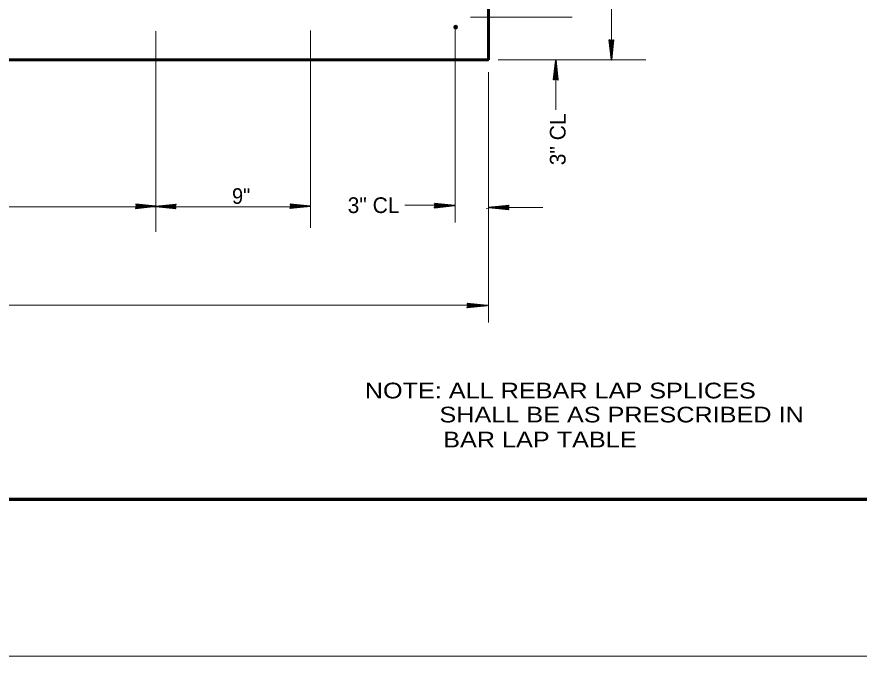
# Model space of a CAD drawing. Extents: x 4.49 to 7.69, y 0.28 to 2.27.
# Drawn here: x 5.2955 to 5.7423, y 0.2828 to 0.6219 of the extents above; entities that cross this region are included whole.
import ezdxf

# ---------------------------------------------------------------- set-up
doc = ezdxf.new("R2010")
doc.units = 0
doc.header["$LTSCALE"] = 0.0033
doc.header["$PDMODE"] = 32
doc.header["$PDSIZE"] = 0.00165
doc.layers.add('1', color=7, linetype='Continuous', lineweight=35)

msp = doc.modelspace()

# ---------------------------------------------------------------- linework, layer by layer
at = {"layer": '1', "lineweight": 13}
for p, q in [((5.610917, 1.013917), (5.610917, 0.599083)), ((5.536083, 0.62175), (5.590083, 0.62175)), ((5.528083, 0.617583), (5.528083, 0.51275)), ((5.369333, 0.61425), (5.369333, 0.512083)), ((5.45125, 0.614583), (5.45125, 0.513417)), ((5.528083, 0.609417), (5.528083, 0.607833)), ((5.54575, 0.599083), (5.54575, 0.59875)), ((5.55075, 0.599083), (5.629083, 0.599083)), ((5.54575, 0.592583), (5.54575, 0.510833)), ((5.581333, 0.572583), (5.581333, 0.589083)), ((5.448417, 0.521167), (4.897333, 0.521167)), ((5.50125, 0.522), (5.522083, 0.522)), ((5.544583, 0.52025), (5.545167, 0.52025)), ((5.55375, 0.52075), (5.574583, 0.52075)), ((5.45125, 0.51575), (5.45125, 0.51)), ((5.369333, 0.513083), (5.369333, 0.507833)), ((5.54575, 0.512417), (5.54575, 0.45975)), ((5.179917, 0.469), (5.545333, 0.469)), ((7.689167, 0.28275), (4.492417, 0.28275))]:
    msp.add_line(p, q, dxfattribs=at)
at = {"layer": '1'}
for p, q in [((5.609833, 0.609417), (5.610667, 0.602083)), ((5.61, 0.609417), (5.61075, 0.602083)), ((5.610083, 0.609417), (5.610917, 0.602083)), ((5.61025, 0.6095), (5.611, 0.602167)), ((5.61175, 0.609417), (5.61075, 0.601583)), ((5.610917, 0.609667), (5.610917, 0.599083)), ((5.61175, 0.609417), (5.610917, 0.601583)), ((5.611917, 0.609417), (5.611, 0.601583)), ((5.611917, 0.609417), (5.611, 0.601583)), ((5.611833, 0.609417), (5.611, 0.601583)), ((5.581333, 0.588417), (5.581333, 0.599)), ((5.580333, 0.588667), (5.58125, 0.5965)), ((5.580333, 0.588667), (5.58125, 0.5965)), ((5.580417, 0.588667), (5.58125, 0.5965)), ((5.5805, 0.588667), (5.581333, 0.5965)), ((5.5805, 0.588667), (5.5815, 0.5965)), ((5.582, 0.588583), (5.58125, 0.595917)), ((5.582167, 0.588667), (5.581333, 0.596)), ((5.58225, 0.588667), (5.5815, 0.596)), ((5.582417, 0.588667), (5.581583, 0.596)), ((5.51725, 0.522833), (5.525083, 0.521917)), ((5.51725, 0.522833), (5.525083, 0.521917)), ((5.51725, 0.52275), (5.525083, 0.521917)), ((5.358583, 0.521417), (5.369167, 0.521417)), ((5.35875, 0.52075), (5.366083, 0.5215)), ((5.358833, 0.522417), (5.366667, 0.5215)), ((5.358833, 0.522417), (5.366667, 0.5215)), ((5.358833, 0.522333), (5.366667, 0.5215)), ((5.358833, 0.52225), (5.366667, 0.521417)), ((5.358833, 0.52225), (5.366667, 0.52125)), ((5.358833, 0.520583), (5.366167, 0.521417)), ((5.358833, 0.5205), (5.366167, 0.52125)), ((5.358833, 0.520333), (5.366167, 0.521167)), ((5.379917, 0.52125), (5.369333, 0.52125)), ((5.379667, 0.520417), (5.371833, 0.521417)), ((5.379667, 0.520417), (5.371833, 0.52125)), ((5.379667, 0.52025), (5.371833, 0.521167)), ((5.379667, 0.52025), (5.371833, 0.521167)), ((5.379667, 0.520333), (5.371833, 0.521167)), ((5.379667, 0.522333), (5.372333, 0.5215)), ((5.379667, 0.522167), (5.372333, 0.521417)), ((5.379667, 0.522083), (5.372333, 0.52125)), ((5.37975, 0.521917), (5.372417, 0.521167)), ((5.4405, 0.5215), (5.451083, 0.5215)), ((5.440667, 0.520833), (5.448, 0.521583)), ((5.44075, 0.5225), (5.448583, 0.521583)), ((5.44075, 0.5225), (5.448583, 0.521583)), ((5.44075, 0.522417), (5.448583, 0.521583)), ((5.44075, 0.522333), (5.448583, 0.5215)), ((5.44075, 0.522333), (5.448583, 0.521333)), ((5.44075, 0.520667), (5.448083, 0.5215)), ((5.44075, 0.520583), (5.448083, 0.521333)), ((5.44075, 0.520417), (5.448083, 0.52125)), ((5.517, 0.521833), (5.527583, 0.521833)), ((5.517167, 0.521167), (5.5245, 0.521917)), ((5.51725, 0.522667), (5.525083, 0.521833)), ((5.51725, 0.522667), (5.525083, 0.521667)), ((5.51725, 0.521), (5.524583, 0.521833)), ((5.51725, 0.520917), (5.524583, 0.521667)), ((5.51725, 0.52075), (5.524583, 0.521583)), ((5.556417, 0.52075), (5.545833, 0.52075)), ((5.556167, 0.519917), (5.548333, 0.520917)), ((5.556167, 0.519917), (5.548333, 0.52075)), ((5.556167, 0.51975), (5.548333, 0.520667)), ((5.556167, 0.51975), (5.548333, 0.520667)), ((5.556167, 0.519833), (5.548333, 0.520667)), ((5.556167, 0.521833), (5.548833, 0.521)), ((5.556167, 0.521667), (5.548833, 0.520917)), ((5.556167, 0.521583), (5.548833, 0.52075)), ((5.55625, 0.521417), (5.548917, 0.520667)), ((5.534583, 0.469833), (5.542417, 0.468917)), ((5.534583, 0.469833), (5.542417, 0.468917)), ((5.534583, 0.46975), (5.542417, 0.468917)), ((5.534583, 0.469667), (5.542417, 0.468833)), ((5.534583, 0.469667), (5.542417, 0.468667)), ((5.534333, 0.468833), (5.544917, 0.468833)), ((5.5345, 0.468167), (5.541833, 0.468917)), ((5.534583, 0.468), (5.541917, 0.468833)), ((5.534583, 0.467917), (5.541917, 0.468667)), ((5.534583, 0.46775), (5.541917, 0.468583))]:
    msp.add_line(p, q, dxfattribs=at)
at = {"layer": '1', "lineweight": 60}
msp.add_line((5.54575, 0.599083), (5.122333, 0.599083), dxfattribs=at)
at = {"layer": '1', "lineweight": 70}
msp.add_line((4.659167, 0.366083), (7.605833, 0.366083), dxfattribs=at)
at = {"layer": '1', "lineweight": 60}
msp.add_lwpolyline([(5.462417, 1.01575), (5.462417, 0.682417), (5.54575, 0.682417), (5.54575, 0.599083)], dxfattribs=at)
at = {"layer": '1', "lineweight": 40}
msp.add_lwpolyline([(4.659167, 0.366083), (7.020833, 0.366083), (7.020833, 0.691167), (7.605833, 0.691167)], dxfattribs=at)
at = {"layer": '1'}
for points in [[(5.612, 0.609667), (5.610917, 0.599083), (5.60975, 0.609667), (5.610917, 0.609083)], [(5.611, 0.608917), (5.611083, 0.60425), (5.611, 0.60425), (5.611, 0.605167), (5.611083, 0.608917), (5.611167, 0.605917), (5.61125, 0.609083), (5.611333, 0.606833), (5.611417, 0.609083), (5.611167, 0.605583), (5.611, 0.600917), (5.61075, 0.601833), (5.61075, 0.600583), (5.61075, 0.608917), (5.610583, 0.6065), (5.610583, 0.609083), (5.611, 0.60375), (5.610333, 0.609083)], [(5.58025, 0.588417), (5.581333, 0.599), (5.5825, 0.588417), (5.581333, 0.589)], [(5.58125, 0.589167), (5.581167, 0.593833), (5.58125, 0.593833), (5.58125, 0.592917), (5.581167, 0.589167), (5.581083, 0.592167), (5.581, 0.589), (5.580917, 0.59125), (5.580833, 0.589), (5.581083, 0.5925), (5.58125, 0.597167), (5.5815, 0.59625), (5.5815, 0.5975), (5.5815, 0.589167), (5.581667, 0.591583), (5.581667, 0.589), (5.58125, 0.594333), (5.581917, 0.589)], [(5.517, 0.522917), (5.527583, 0.521833), (5.517, 0.520667), (5.517583, 0.521833)], [(5.358583, 0.5225), (5.369167, 0.521417), (5.358583, 0.52025), (5.359167, 0.521417)], [(5.359333, 0.5215), (5.364, 0.521583), (5.364, 0.5215), (5.363083, 0.5215), (5.359333, 0.521583), (5.362333, 0.521667), (5.359167, 0.52175), (5.361417, 0.521833), (5.359167, 0.521917), (5.362667, 0.521667), (5.367333, 0.5215), (5.366417, 0.52125), (5.367667, 0.52125), (5.359333, 0.52125), (5.36175, 0.521083), (5.359167, 0.521083), (5.3645, 0.5215), (5.359167, 0.520833)], [(5.379917, 0.520167), (5.369333, 0.52125), (5.379917, 0.522417), (5.379333, 0.52125)], [(5.379167, 0.521167), (5.3745, 0.521083), (5.3745, 0.521167), (5.375417, 0.521167), (5.379167, 0.521083), (5.376167, 0.521), (5.379333, 0.520917), (5.377083, 0.520833), (5.379333, 0.52075), (5.375833, 0.521), (5.371167, 0.521167), (5.372083, 0.521417), (5.370833, 0.521417), (5.379167, 0.521417), (5.37675, 0.521583), (5.379333, 0.521583), (5.374, 0.521167), (5.379333, 0.521833)], [(5.4405, 0.522583), (5.451083, 0.5215), (5.4405, 0.520333), (5.441083, 0.5215)], [(5.44125, 0.521583), (5.445917, 0.521667), (5.445917, 0.521583), (5.445, 0.521583), (5.44125, 0.521667), (5.44425, 0.52175), (5.441083, 0.521833), (5.443333, 0.521917), (5.441083, 0.522), (5.444583, 0.52175), (5.44925, 0.521583), (5.448333, 0.521333), (5.449583, 0.521333), (5.44125, 0.521333), (5.443667, 0.521167), (5.441083, 0.521167), (5.446417, 0.521583), (5.441083, 0.520917)], [(5.51775, 0.521917), (5.522417, 0.522), (5.522417, 0.521917), (5.5215, 0.521917), (5.51775, 0.522), (5.52075, 0.522083), (5.517583, 0.522167), (5.519833, 0.52225), (5.517583, 0.522333), (5.521083, 0.522083), (5.52575, 0.521917), (5.524833, 0.521667), (5.526083, 0.521667), (5.51775, 0.521667), (5.520167, 0.5215), (5.517583, 0.5215), (5.522917, 0.521917), (5.517583, 0.52125)], [(5.556417, 0.519667), (5.545833, 0.52075), (5.556417, 0.521917), (5.555833, 0.52075)], [(5.555667, 0.520667), (5.551, 0.520583), (5.551, 0.520667), (5.551917, 0.520667), (5.555667, 0.520583), (5.552667, 0.5205), (5.555833, 0.520417), (5.553583, 0.520333), (5.555833, 0.52025), (5.552333, 0.5205), (5.547667, 0.520667), (5.548583, 0.520917), (5.547333, 0.520917), (5.555667, 0.520917), (5.55325, 0.521083), (5.555833, 0.521083), (5.5505, 0.520667), (5.555833, 0.521333)], [(5.534333, 0.469917), (5.544917, 0.468833), (5.534333, 0.467667), (5.534917, 0.468833)], [(5.535083, 0.468917), (5.53975, 0.469), (5.53975, 0.468917), (5.538833, 0.468917), (5.535083, 0.469), (5.538083, 0.469083), (5.534917, 0.469167), (5.537167, 0.46925), (5.534917, 0.469333), (5.538417, 0.469083), (5.543083, 0.468917), (5.542167, 0.468667), (5.543417, 0.468667), (5.535083, 0.468667), (5.5375, 0.4685), (5.534917, 0.4685), (5.54025, 0.468917), (5.534917, 0.46825)]]:
    msp.add_lwpolyline(points, close=True, dxfattribs=at)
for points in [[(5.611, 0.608917), (5.61175, 0.609333), (5.6115, 0.609083), (5.611167, 0.608917), (5.61125, 0.608667), (5.611583, 0.608833), (5.610833, 0.609), (5.610333, 0.609167), (5.609917, 0.609417)], [(5.58125, 0.589167), (5.5805, 0.58875), (5.58075, 0.589), (5.581083, 0.589167), (5.581, 0.589417), (5.580667, 0.58925), (5.581417, 0.589083), (5.581917, 0.588917), (5.582333, 0.588667)], [(5.359333, 0.5215), (5.358917, 0.52225), (5.359167, 0.522), (5.359333, 0.521667), (5.359583, 0.52175), (5.359417, 0.522083), (5.35925, 0.521333), (5.359083, 0.520833), (5.358833, 0.520417)], [(5.379167, 0.521167), (5.379583, 0.520417), (5.379333, 0.520667), (5.379167, 0.521), (5.378917, 0.520917), (5.379083, 0.520583), (5.37925, 0.521333), (5.379417, 0.521833), (5.379667, 0.52225)], [(5.44125, 0.521583), (5.440833, 0.522333), (5.441083, 0.522083), (5.44125, 0.52175), (5.4415, 0.521833), (5.441333, 0.522167), (5.441167, 0.521417), (5.441, 0.520917), (5.44075, 0.5205)], [(5.51775, 0.521917), (5.517333, 0.522667), (5.517583, 0.522417), (5.51775, 0.522083), (5.518, 0.522167), (5.517833, 0.5225), (5.517667, 0.52175), (5.5175, 0.52125), (5.51725, 0.520833)], [(5.555667, 0.520667), (5.556083, 0.519917), (5.555833, 0.520167), (5.555667, 0.5205), (5.555417, 0.520417), (5.555583, 0.520083), (5.55575, 0.520833), (5.555917, 0.521333), (5.556167, 0.52175)], [(5.535083, 0.468917), (5.534667, 0.469667), (5.534917, 0.469417), (5.535083, 0.469083), (5.535333, 0.469167), (5.535167, 0.4695), (5.535, 0.46875), (5.534833, 0.46825), (5.534583, 0.467833)]]:
    msp.add_lwpolyline(points, dxfattribs=at)
msp.add_point((5.528333, 0.616417), dxfattribs=at)

# ---------------------------------------------------------------- texts
msp.add_text('3" CL', height=0.008334, rotation=90, dxfattribs=at).set_placement((5.586583, 0.543167))
for s, width, p in [('9"', 0.95, (5.409667, 0.522667)), ('NOTE: ALL REBAR LAP SPLICES', 1.2, (5.480083, 0.4195)), ('SHALL BE AS PRESCRIBED IN', 1.2, (5.519667, 0.40675)), ('BAR LAP TABLE', 1.2, (5.521667, 0.3935))]:
    msp.add_text(s, height=0.008334, dxfattribs=dict(at, width=width)).set_placement(p)
msp.add_text('3" CL', height=0.008334, dxfattribs=at).set_placement((5.471, 0.517833))

doc.saveas('drawing.dxf')
